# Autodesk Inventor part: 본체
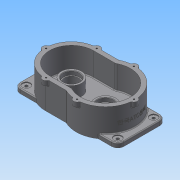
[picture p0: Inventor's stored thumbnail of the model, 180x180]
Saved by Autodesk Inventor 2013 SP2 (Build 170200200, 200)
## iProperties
Created: 2025-09
Part Number: 본체
Material: Generic
Document SubType Name: Modeling
Designer: a
Density: 1 g/cm^3
Author: a
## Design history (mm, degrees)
sketch "스케치1"
  geometry: L1 (-104.5, -55)-(104.5, -55); L2 (118.5, -41)-(118.5, 41); L3 (104.5, 55)-(-104.5, 55); L4 (-118.5, 41)-(-118.5, -41); L5 (-118.5, -55)-(118.5, 55); L6 (118.5, -55)-(-118.5, 55); A1 r 14 centre (-104.5, 41) between (-104.5, 55) and (-118.5, 41); A2 r 14 centre (104.5, 41) between (118.5, 41) and (104.5, 55); A3 r 14 centre (104.5, -41) between (104.5, -55) and (118.5, -41); A4 r 14 centre (-104.5, -41) between (-118.5, -41) and (-104.5, -55); 1 further point
  constraints: 12 end point, 8 point on circle, 8 point on line, 8 tangent, 4 centre point, 2 equal radius, 2 midpoint, 2 parallel, 1 horizontal, 1 perpendicular
  dimensions: "d0" = 237 distance of L5.end L6.end; "d2" = 110 distance of L6.start L5.end; "d3" = 14 radius of A1; "d4" = 14 radius of A2
extrude "돌출1" new body sketch "스케치1" distance "d5" = 10; taper "d6" = 0 deg
sketch "스케치2"
  geometry: L1 (118.5, 41)-(118.5, -41) reference; L2 (104.5, -55)-(-104.5, -55) reference; L3 (-118.5, -41)-(-118.5, 41) reference; L4 (-104.5, 55)-(104.5, 55) reference; L5 (-42.5, 50)-(8.132, 50); L6 (-42.5, -50)-(8.132, -50); L7 (-42.5, 60)-(5.684, 60); L8 (5.684, -60)-(-42.5, -60); A1 r 14 centre (104.5, 41) between (118.5, 41) and (104.5, 55) reference; A2 r 14 centre (104.5, -41) between (104.5, -55) and (118.5, -41) reference; A3 r 14 centre (-104.5, -41) between (-118.5, -41) and (-104.5, -55) reference; A4 r 14 centre (-104.5, 41) between (-104.5, 55) and (-118.5, 41) reference; A5 r 57 centre (35.5, 0) between (8.132, -50) and (8.132, 50); A6 r 50 centre (-42.5, 0) between (-42.5, 50) and (-42.5, -50); A7 r 60 centre (-42.5, 0) between (-42.5, 60) and (-42.5, -60); A8 r 67 centre (35.5, 0) between (5.684, -60) and (5.684, 60); 1 further point
  constraints: 8 end point, 8 point on circle, 4 centre point, 3 parallel, 2 horizontal alignment, 2 tangent, 3 other
  dimensions: "d7" = 114 diameter of A5; "d10" = 100 diameter of A6; "d11" = 76 distance from line of A6.centre L3; "d12" = 78 distance of A5.centre A6.centre; "d13" = 10 distance between parallel lines of L7 L5
  node "절단 모서리 투영1"
extrude "돌출2" join sketch "스케치2" distance "d14" = 64; taper "d15" = 0 deg
sketch "스케치3"
  geometry: L1 (8.132, 50)-(-42.5, 50) reference; L2 (-42.5, -50)-(8.132, -50) reference; L3 (118.5, 41)-(118.5, -41) reference; L4 (104.5, -55)-(73.762, -55) reference; L5 (5.684, -60)-(-42.5, -60) reference; L6 (-66.479, -55)-(-104.5, -55) reference; L7 (-118.5, -41)-(-118.5, 41) reference; L8 (-104.5, 55)-(-66.479, 55) reference; L9 (73.762, 55)-(104.5, 55) reference; L10 (-42.5, 60)-(5.684, 60) reference; L11 (50.467, -55)-(20.533, -55) reference; L12 (20.533, 55)-(50.467, 55) reference; C1 r 23.5 at (-42.5, 0); C2 r 23.5 at (35.5, 0); A1 r 50 centre (-42.5, 0) between (-42.5, 50) and (-42.5, -50) reference; A2 r 14 centre (104.5, 41) between (118.5, 41) and (104.5, 55) reference; A3 r 14 centre (104.5, -41) between (104.5, -55) and (118.5, -41) reference; A4 r 67 centre (35.5, 0) between (5.684, -60) and (73.762, -55) reference; A5 r 60 centre (-42.5, 0) between (-66.479, -55) and (-42.5, -60) reference; A6 r 14 centre (-104.5, -41) between (-118.5, -41) and (-104.5, -55) reference; A7 r 14 centre (-104.5, 41) between (-104.5, 55) and (-118.5, 41) reference; A8 r 60 centre (-42.5, 0) between (-66.479, 55) and (-66.479, -55) reference; A9 r 67 centre (35.5, 0) between (73.762, 55) and (5.684, 60) reference; A10 r 60 centre (-42.5, 0) between (-42.5, 60) and (-66.479, 55) reference; A11 r 67 centre (35.5, 0) between (73.762, -55) and (73.762, 55) reference; A12 r 57 centre (35.5, 0) between (8.132, -50) and (20.533, -55) reference; A13 r 57 centre (35.5, 0) between (20.533, -55) and (50.467, -55) reference; A14 r 57 centre (35.5, 0) between (50.467, -55) and (50.467, 55) reference; A15 r 57 centre (35.5, 0) between (50.467, 55) and (20.533, 55) reference; A16 r 57 centre (35.5, 0) between (20.533, 55) and (8.132, 50) reference; 1 further point
  constraints: 2 centre point, 2 coincident
  dimensions: "d16" = 47 diameter of C1; "d17" = 47 diameter of C2
  node "절단 모서리 투영2"
extrude "돌출3" join sketch "스케치3" distance "d18" = 12; taper "d19" = 0 deg
extrude "돌출4" join sketch "스케치2" distance "d20" = 10; taper "d21" = 0 deg
extrude "돌출5" join sketch "스케치3" distance "d22" = 26; taper "d23" = 0 deg
hole "구멍1" diameter "d26" = 6.6; stored, may be unused: countersink angle "d30" = 90 deg, drill point angle "d32" = 118 deg; dims "d24" = 10, "d25" = 10, "d27" = 6, "d28" = 18, "d29" = 2, "d31" = 8
hole "구멍2" diameter "d35" = 6.6; stored, may be unused: countersink angle "d39" = 90 deg, drill point angle "d41" = 118 deg; dims "d33" = 10, "d34" = 10, "d36" = 6, "d37" = 18, "d38" = 2, "d40" = 8
hole "구멍3" diameter "d44" = 6.6; stored, may be unused: countersink angle "d48" = 90 deg, drill point angle "d50" = 118 deg; dims "d42" = 10, "d43" = 10, "d45" = 6, "d46" = 18, "d47" = 2, "d49" = 8
hole "구멍4" diameter "d53" = 6.6; stored, may be unused: countersink angle "d57" = 90 deg, drill point angle "d59" = 118 deg; dims "d51" = 10, "d52" = 10, "d54" = 6, "d55" = 18, "d56" = 2, "d58" = 8
hole "구멍5" diameter "d62" = 32; stored, may be unused: countersink angle "d66" = 90 deg, drill point angle "d68" = 0 deg; dims "d63" = 6, "d64" = 37, "d65" = 9, "d67" = 16, "d69" = 10, "d70" = 10
hole "구멍6" diameter "d73" = 28; stored, may be unused: countersink angle "d77" = 90 deg, drill point angle "d79" = 0 deg; dims "d71" = 10, "d72" = 10, "d74" = 6, "d75" = 4, "d76" = 2, "d78" = 3
hole "구멍7" diameter "d82" = 30; stored, may be unused: countersink angle "d86" = 90 deg, drill point angle "d88" = 0 deg; dims "d83" = 6, "d84" = 37, "d85" = 9, "d87" = 30, "d183" = 10, "d184" = 10
hole "구멍8" diameter "d91" = 35; stored, may be unused: countersink angle "d95" = 90 deg, drill point angle "d97" = 0 deg; dims "d89" = 10, "d90" = 10, "d92" = 6, "d93" = 37, "d94" = 9, "d96" = 8.3
chamfer "모따기1" distance "d98" = 0.8; stored, may be unused: second distance "d99" = 2, angle "d100" = 30 deg
fillet "모깎기1" dims "d101" = 0.3
chamfer "모따기2" distance "d102" = 1; stored, may be unused: second distance "d103" = 2, angle "d104" = 45 deg
sketch "스케치4"
  geometry: C1 r 8 at (-100.5, 0); C2 r 8 at (-42.5, 58); C3 r 8 at (-42.5, -58); C4 r 8 at (35.5, -65); C5 r 8 at (35.5, 65); C6 r 8 at (100.5, 0); A1 r 57 centre (35.5, 0) between (8.132, -50) and (8.132, 50) reference; A2 r 50 centre (-42.5, 0) between (-42.5, 50) and (-42.5, -50) reference; A3 r 67 centre (35.5, 0) between (5.684, -60) and (5.684, 60) reference; 1 further point
  constraints: 6 centre point, 3 vertical alignment, 2 horizontal alignment
  dimensions: "d105" = 16 diameter of C1; "d106" = 16 diameter of C2; "d107" = 16 diameter of C3; "d108" = 16 diameter of C5; "d109" = 16 diameter of C6; "d110" = 16 diameter of C4; "d111" = 116 distance of C3.centre C2.centre; "d112" = 58 distance of A2.centre C3.centre; "d113" = 58 distance of A2.centre C1.centre; "d114" = 78 horizontal distance of C3.centre C4.centre; "d115" = 130 distance of C5.centre C4.centre; "d116" = 65 distance of C5.centre A1.centre; "d117" = 65 distance of A1.centre C6.centre
extrude "돌출6" join sketch "스케치4" distance "d118" = 12; taper "d119" = 0 deg
hole "구멍9" diameter "d122" = 3.242; stored, may be unused: countersink angle "d126" = 90 deg, drill point angle "d128" = 118 deg; dims "d120" = 10, "d121" = 10, "d123" = 8, "d124" = 37, "d125" = 9, "d127" = 10
hole "구멍10" diameter "d131" = 3.242; stored, may be unused: countersink angle "d135" = 90 deg, drill point angle "d137" = 118 deg; dims "d129" = 10, "d130" = 10, "d132" = 8, "d133" = 37, "d134" = 9, "d136" = 10
hole "구멍11" diameter "d140" = 3.242; stored, may be unused: countersink angle "d144" = 90 deg, drill point angle "d146" = 118 deg; dims "d138" = 10, "d139" = 10, "d141" = 8, "d142" = 37, "d143" = 9, "d145" = 10
hole "구멍12" diameter "d149" = 3.242; stored, may be unused: countersink angle "d153" = 90 deg, drill point angle "d155" = 118 deg; dims "d147" = 10, "d148" = 10, "d150" = 8, "d151" = 37, "d152" = 9, "d154" = 10
hole "구멍13" diameter "d158" = 3.242; stored, may be unused: countersink angle "d162" = 90 deg, drill point angle "d164" = 118 deg; dims "d156" = 10, "d157" = 10, "d159" = 8, "d160" = 37, "d161" = 9, "d163" = 10
hole "구멍14" diameter "d167" = 3.242; stored, may be unused: countersink angle "d171" = 90 deg, drill point angle "d173" = 118 deg; dims "d165" = 10, "d166" = 10, "d168" = 8, "d169" = 37, "d170" = 9, "d172" = 10
sketch "스케치6"
  geometry: L1 (0, 82)-(0, 0) reference; L2 (-10, 0)-(-10, 82) reference; L3 (0, 82)-(-10, 82) reference; L4 (0, 82)-(0, 0) reference; L5 (0, 0)-(-10, 0) reference; L6 (-40, 5)-(-40, 77); L7 (-40, 77)-(-20, 77); L8 (-20, 77)-(-20, 5); L9 (-20, 5)-(-40, 5); 3 further points
  constraints: 2 midpoint, 1 horizontal alignment, 1 parallel, 2 other
  dimensions: "d174" = 20 distance of L8.end L6.start; "d176" = 20 horizontal distance of point (0, 41) L8.end; "d177" = 72 distance of L6.start L6.end
feature "엠보싱1" sketch "스케치6" dims "d0" = 237, "d2" = 110, "d3" = 14, "d4" = 14, "d7" = 114, "d178" = 0.5, "d179" = 0
fillet "모깎기2" dims "d180" = 2
fillet "모깎기3" dims "d181" = 13
fillet "모깎기4" dims "d182" = 2
node "솔리드1"
node "절단 모서리 투영4"
